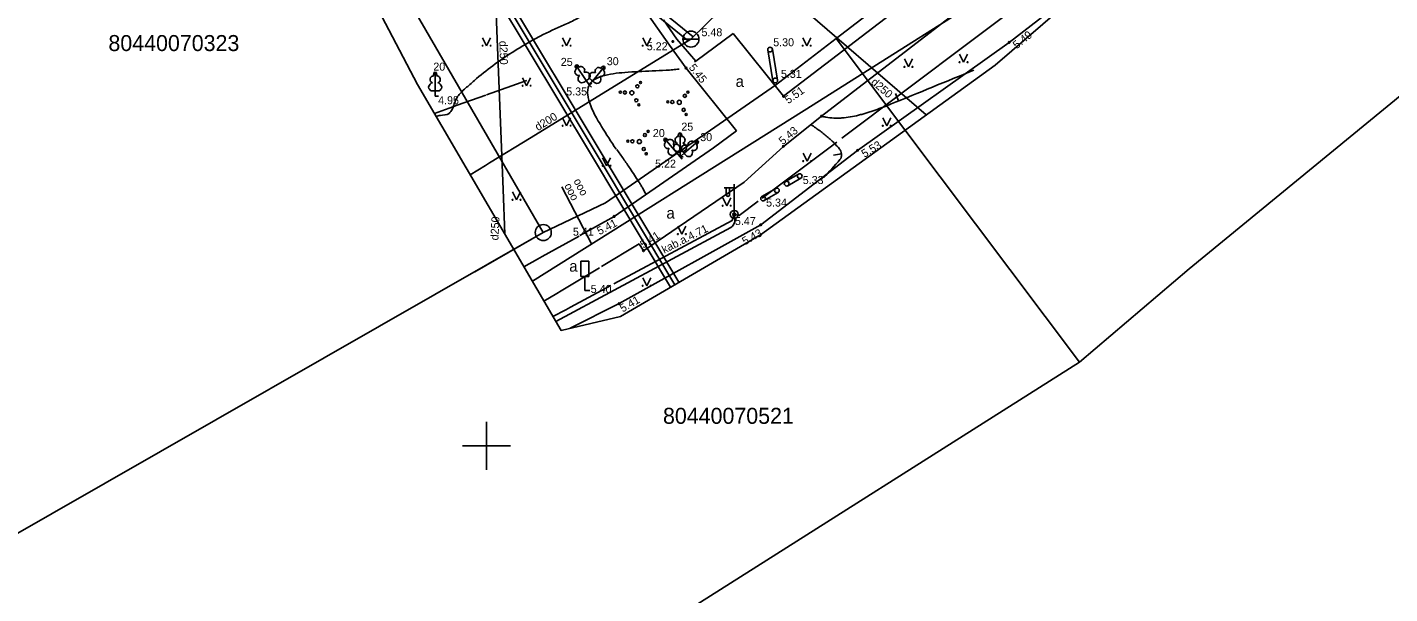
# Model space of a CAD drawing. Extents: x 519536 to 519949, y 326041 to 326519.
# Drawn here: x 519771.3 to 519856.4, y 326090.7 to 326126.2 of the extents above; entities that cross this region are included whole.
import ezdxf

# ---------------------------------------------------------------- set-up
doc = ezdxf.new("R2010")
doc.units = 0
for name, color, linetype in [('APGR_ELEM_####_####_#', 7, 'Continuous'), ('APGR_SARK_####_####_#', 7, 'Continuous'), ('APGS_ELEM_####_####_#', 7, 'Continuous'), ('APGS_VADP_ZSPR_####_#', 7, 'Continuous'), ('APGS_VADP_ZSPR_####_I', 7, 'Continuous'), ('APGS_VADP_ZSPR_TKST_I', 7, 'Continuous'), ('BUVE_ELEM_####_####_#', 7, 'Continuous'), ('CELI_CMAL_####_####_#', 7, 'Continuous'), ('CELI_CSEG_####_TKST_#', 7, 'Continuous'), ('CELI_ELEM_####_####_#', 7, 'Continuous'), ('CELI_SEGL_####_####_#', 7, 'Continuous'), ('CELI_ZIME_####_####_#', 7, 'Continuous'), ('GEOD_ELEM_####_####_#', 7, 'Continuous'), ('RAMI_UZMR_####_####_#', 7, 'Continuous'), ('RELJ_AATZ_####_TKST_#', 7, 'Continuous'), ('RELJ_ELEM_####_####_#', 7, 'Continuous'), ('RELJ_HORZ_PAMT_####_#', 7, 'Continuous'), ('ROBZ_PROJ_####_####_#', 7, 'Continuous'), ('ROBZ_PROJ_####_TKST_#', 7, 'Continuous'), ('ROBZ_UZMR_####_####_#', 7, 'Continuous'), ('ROBZ_UZMR_####_TKST_#', 7, 'Continuous'), ('SAKK_IZVK_####_TKST_#', 7, 'Continuous'), ('SAKK_KKAN_####_####_#', 7, 'Continuous'), ('SAKT_VADP_NEDR_####_#', 7, 'Continuous'), ('SKAN_VADP_PAST_####_#', 7, 'Continuous'), ('SKAN_VADP_PAST_####_I', 7, 'Continuous'), ('SKAN_VADP_PAST_TKST_#', 7, 'Continuous'), ('SKAN_VADP_PAST_TKST_I', 7, 'Continuous'), ('TERT_DIAM_####_TKST_#', 7, 'Continuous'), ('TERT_ELEM_####_####_#', 7, 'Continuous'), ('TERT_KONT_####_####_#', 7, 'Continuous'), ('TERT_KRND_####_####_#', 7, 'Continuous'), ('UDTK_ELEM_####_####_#', 7, 'Continuous'), ('UDTK_ELEM_####_TKST_#', 7, 'Continuous'), ('UDTK_VADP_UDEN_####_#', 7, 'Continuous'), ('UDTK_VADP_UDEN_TKST_#', 7, 'Continuous')]:
    doc.layers.add(name, color=color, linetype=linetype)

msp = doc.modelspace()

# ---------------------------------------------------------------- linework, layer by layer
at = {"layer": 'APGR_ELEM_####_####_#'}
msp.add_circle((519803.54, 326113.32), 0.5, dxfattribs=at)
at = {"layer": 'APGR_SARK_####_####_#'}
for p, q in [((519803.539, 326113.32), (519783.534, 326147.79)), ((519799.257, 326110.872), (519803.539, 326113.32))]:
    msp.add_line(p, q, dxfattribs=at)
at = {"layer": 'APGS_ELEM_####_####_#'}
for p, q in [((519815.476, 326116.123), (519814.841, 326116.118)), ((519814.976, 326116.119), (519814.976, 326115.727)), ((519815.186, 326116.121), (519815.186, 326115.727)), ((519815.476, 326114.456), (519815.476, 326116.339))]:
    msp.add_line(p, q, dxfattribs=at)
for radius in [0.25, 0.09]:
    msp.add_circle((519815.476, 326114.456), radius, dxfattribs=at)
msp.add_ellipse((519815.081, 326115.727), major_axis=(0, 0.151), ratio=0.695971, start_param=1.570796, end_param=4.712389, dxfattribs=at)
at = {"layer": 'APGS_VADP_ZSPR_####_#'}
for p, q in [((519817.215, 326115.469), (519821.877, 326118.979)), ((519815.786, 326114.393), (519816.972, 326115.286)), ((519807.949, 326110.114), (519815.34, 326114.084)), ((519815.34, 326114.084), (519815.476, 326114.456)), ((519815.476, 326114.456), (519815.786, 326114.393)), ((519805.237, 326108.657), (519807.759, 326110.012)), ((519804.144, 326108.071), (519804.943, 326108.5)), ((519804.943, 326108.499), (519805.237, 326108.657))]:
    msp.add_line(p, q, dxfattribs=at)
msp.add_lwpolyline([(519822.193, 326119.217), (519834.343, 326128.364), (519835.607, 326129.316)], dxfattribs=at)
at = {"layer": 'APGS_VADP_ZSPR_####_I'}
for points in [[(519815.511, 326114.135), (519815.506, 326113.991), (519815.457, 326113.848), (519815.367, 326113.726), (519815.251, 326113.64)], [(519815.511, 326114.135), (519815.476, 326114.456)], [(519804.322, 326107.766), (519815.251, 326113.64)]]:
    msp.add_lwpolyline(points, dxfattribs=at)
at = {"layer": 'BUVE_ELEM_####_####_#'}
for centre in [(519817.71, 326124.758), (519818.036, 326122.824), (519819.569, 326116.852), (519818.141, 326115.954), (519818.751, 326116.378), (519817.278, 326115.446)]:
    msp.add_circle(centre, 0.148, dxfattribs=at)
at = {"layer": 'CELI_CMAL_####_####_#'}
for p, q in [((519815.478, 326125.668), (519815.4, 326125.765)), ((519818.554, 326121.841), (519815.4, 326125.765)), ((519815.612, 326119.681), (519812.465, 326123.597)), ((519808.282, 326108.879), (519817.13, 326113.802)), ((519809.798, 326112.186), (519809.533, 326112.624)), ((519803.58, 326109.036), (519804.379, 326109.511)), ((519805.225, 326107.34), (519808.282, 326108.879))]:
    msp.add_line(p, q, dxfattribs=at)
for points in [[(519803.048, 326140.696), (519806.405, 326132.206), (519810.67, 326126.102)], [(519818.554, 326121.841), (519828.619, 326129.557), (519832.661, 326132.764)], [(519834.281, 326130.959), (519829.979, 326127.581), (519820.927, 326120.594)], [(519823.18, 326118.459), (519832.654, 326125.205), (519836.503, 326128.205)], [(519810.67, 326126.102), (519811.417, 326125.034), (519812.465, 326123.597)], [(519811.049, 326126.606), (519811.891, 326125.402), (519813.064, 326124.039)], [(519813.064, 326124.039), (519815.4, 326125.765)], [(519820.927, 326120.594), (519818.542, 326118.707), (519816.086, 326116.475)], [(519815.612, 326119.681), (519814.169, 326118.621)], [(519814.169, 326118.621), (519807.967, 326114.328)], [(519823.18, 326118.459), (519817.13, 326113.802)], [(519816.086, 326116.475), (519809.798, 326112.186)], [(519805.824, 326113.134), (519807.967, 326114.328)], [(519803.464, 326111.818), (519805.773, 326113.105)], [(519807.182, 326111.204), (519809.533, 326112.624)], [(519802.327, 326111.184), (519803.181, 326111.66)], [(519803.181, 326111.66), (519803.464, 326111.818)], [(519804.662, 326109.682), (519807.046, 326111.122)], [(519804.379, 326109.511), (519804.662, 326109.682)]]:
    msp.add_lwpolyline(points, dxfattribs=at)
at = {"layer": 'CELI_ELEM_####_####_#'}
for p, q in [((519806.381, 326111.537), (519805.881, 326111.537)), ((519805.881, 326110.568), (519805.881, 326111.537)), ((519806.381, 326110.568), (519806.381, 326111.537)), ((519806.381, 326110.568), (519805.881, 326110.568)), ((519806.135, 326110.568), (519806.135, 326109.69)), ((519806.135, 326109.69), (519806.45, 326109.69))]:
    msp.add_line(p, q, dxfattribs=at)
at = {"layer": 'CELI_SEGL_####_####_#'}
msp.add_line((519812.999, 326123.991), (519813.064, 326124.039), dxfattribs=at)
at = {"layer": 'CELI_ZIME_####_####_#'}
for p, q in [((519817.564, 326124.733), (519817.89, 326122.799)), ((519817.856, 326124.782), (519818.182, 326122.848)), ((519818.677, 326116.506), (519819.495, 326116.98)), ((519818.826, 326116.25), (519819.643, 326116.724)), ((519818.066, 326116.082), (519817.203, 326115.574)), ((519818.217, 326115.827), (519817.353, 326115.318))]:
    msp.add_line(p, q, dxfattribs=at)
at = {"layer": 'GEOD_ELEM_####_####_#'}
for p, q in [((519800, 326101.5), (519800, 326100)), ((519798.5, 326100), (519800, 326100)), ((519800, 326100), (519800, 326098.5)), ((519800, 326100), (519801.5, 326100))]:
    msp.add_line(p, q, dxfattribs=at)
at = {"layer": 'RAMI_UZMR_####_####_#'}
msp.add_lwpolyline([(519873.021, 326209.453), (519881.37, 326184.273), (519884.229, 326177.508), (519883.353, 326172.044), (519868.284, 326155.201), (519831.787, 326123.789), (519817.117, 326113.183), (519808.359, 326108.08), (519804.649, 326107.204), (519795.685, 326122.565), (519782.956, 326146.875), (519761.4, 326134.85), (519741.243, 326123.664), (519728.435, 326146.148), (519720.513, 326144.604), (519669.064, 326119.018)], dxfattribs=at)
at = {"layer": 'RELJ_ELEM_####_####_#'}
for centre in [(519811.636, 326125.262), (519832.654, 326125.205), (519812.465, 326123.597), (519818.554, 326121.841), (519820.927, 326120.594), (519818.542, 326118.707), (519823.18, 326118.459), (519807.967, 326114.328), (519817.13, 326113.802), (519809.798, 326112.186), (519808.282, 326108.879)]:
    msp.add_circle(centre, 0.05, dxfattribs=at)
at = {"layer": 'RELJ_HORZ_PAMT_####_#'}
for p, q in [((519825.541, 326122.006), (519825.73, 326121.543)), ((519821.673, 326118.167), (519822.168, 326118.238))]:
    msp.add_line(p, q, dxfattribs=at)
for points in [[(519796.84, 326120.586), (519797.106, 326120.637), (519797.649, 326120.767), (519797.761, 326120.883), (519797.899, 326121.146), (519798, 326121.429), (519798.111, 326121.704), (519798.278, 326121.943), (519798.817, 326122.459), (519799.373, 326122.95), (519800.535, 326123.859), (519801.756, 326124.681), (519803.031, 326125.424), (519803.766, 326125.808), (519804.518, 326126.15), (519805.271, 326126.495), (519806.008, 326126.888), (519806.456, 326127.174), (519806.885, 326127.487), (519807.66, 326128.203)], [(519820.932, 326120.598), (519820.943, 326120.595), (519821.07, 326120.56), (519821.198, 326120.532), (519821.7, 326120.476), (519821.952, 326120.472), (519822.203, 326120.483), (519822.725, 326120.543), (519823.241, 326120.655), (519823.504, 326120.727), (519823.764, 326120.803), (519824.021, 326120.884), (519824.276, 326120.972), (519824.781, 326121.16), (519825.271, 326121.356), (519830.45, 326123.47)], [(519821.06, 326116.75), (519822.082, 326117.887), (519822.108, 326117.92), (519822.129, 326117.958), (519822.145, 326117.998), (519822.159, 326118.039), (519822.169, 326118.085), (519822.174, 326118.132), (519822.17, 326118.224), (519822.125, 326118.409), (519822.085, 326118.493), (519822.035, 326118.566), (519821.928, 326118.69), (519821.818, 326118.811), (519821.704, 326118.928), (519821.586, 326119.041), (519821.344, 326119.26), (519821.092, 326119.468), (519820.963, 326119.568), (519820.833, 326119.668), (519820.568, 326119.861), (519820.267, 326120.072)]]:
    msp.add_spline(points, degree=3, dxfattribs=at)
at = {"layer": 'ROBZ_PROJ_####_####_#'}
for p, q in [((519821.833, 326125.441), (519831.642, 326133.008)), ((519818.058, 326122.529), (519821.833, 326125.441)), ((519821.833, 326125.441), (519837.056, 326105.226)), ((519860.226, 326124.449), (519843.903, 326111.053)), ((519807.437, 326115.177), (519818.058, 326122.529)), ((519803.539, 326113.32), (519807.437, 326115.177)), ((519764.294, 326090.885), (519803.539, 326113.32)), ((519843.903, 326111.053), (519837.056, 326105.226)), ((519837.056, 326105.226), (519812.114, 326089.425))]:
    msp.add_line(p, q, dxfattribs=at)
at = {"layer": 'ROBZ_UZMR_####_####_#'}
for p, q in [((519803.539, 326113.32), (519783.534, 326147.79)), ((519831.642, 326133.008), (519821.833, 326125.441)), ((519821.833, 326125.441), (519818.058, 326122.529)), ((519818.058, 326122.529), (519807.437, 326115.177)), ((519807.437, 326115.177), (519803.539, 326113.32)), ((519803.539, 326113.32), (519764.294, 326090.885))]:
    msp.add_line(p, q, dxfattribs=at)
at = {"layer": 'SAKK_IZVK_####_TKST_#'}
msp.add_line((519804.705, 326116.186), (519806.567, 326112.566), dxfattribs=at)
at = {"layer": 'SAKK_KKAN_####_####_#'}
msp.add_lwpolyline([(519802.857, 326110.275), (519819.847, 326120.948), (519840.354, 326133.938)], dxfattribs=at)
at = {"layer": 'SAKT_VADP_NEDR_####_#'}
for p, q in [((519797.926, 326133.126), (519806.771, 326118.375)), ((519798.112, 326133.4), (519807.038, 326118.511)), ((519798.299, 326131.921), (519806.549, 326118.161))]:
    msp.add_line(p, q, dxfattribs=at)
for points in [[(519806.771, 326118.375), (519811.756, 326110.06)], [(519807.038, 326118.511), (519812.015, 326110.211)], [(519806.549, 326118.161), (519811.497, 326109.909)]]:
    msp.add_lwpolyline(points, dxfattribs=at)
at = {"layer": 'SKAN_VADP_PAST_####_#'}
for p, q in [((519801.028, 326116.009), (519800.501, 326129.281)), ((519801.139, 326113.219), (519801.028, 326116.009))]:
    msp.add_line(p, q, dxfattribs=at)
at = {"layer": 'SKAN_VADP_PAST_####_I'}
msp.add_lwpolyline([(519827.476, 326120.673), (519818.86, 326128.106), (519818.447, 326128.393)], dxfattribs=at)
at = {"layer": 'TERT_ELEM_####_####_#'}
for p, q in [((519799.75, 326125.5), (519800, 326125)), ((519800, 326125), (519800.25, 326125.5)), ((519804.75, 326125.5), (519805, 326125)), ((519805, 326125), (519805.25, 326125.5)), ((519809.75, 326125.5), (519810, 326125)), ((519810, 326125), (519810.25, 326125.5)), ((519819.75, 326125.5), (519820, 326125)), ((519820, 326125), (519820.25, 326125.5)), ((519829.555, 326124.463), (519829.805, 326123.963)), ((519829.805, 326123.963), (519830.055, 326124.463)), ((519826.107, 326124.173), (519826.357, 326123.673)), ((519826.357, 326123.673), (519826.607, 326124.173)), ((519802.25, 326123), (519802.5, 326122.5)), ((519802.5, 326122.5), (519802.75, 326123)), ((519806.213, 326122.832), (519806.406, 326122.544)), ((519806.626, 326122.812), (519806.406, 326122.544)), ((519806.406, 326122.544), (519806.572, 326122.655)), ((519806.406, 326122.544), (519806.561, 326122.417)), ((519796.782, 326122.188), (519796.782, 326121.841)), ((519796.782, 326121.841), (519796.982, 326121.841)), ((519804.75, 326120.5), (519805, 326120)), ((519805, 326120), (519805.25, 326120.5)), ((519824.75, 326120.5), (519825, 326120)), ((519825, 326120), (519825.25, 326120.5)), ((519811.858, 326118.323), (519812.084, 326118.06)), ((519812.084, 326118.407), (519812.084, 326118.06)), ((519812.347, 326118.286), (519812.084, 326118.06)), ((519819.787, 326118.29), (519820.037, 326117.79)), ((519820.037, 326117.79), (519820.287, 326118.29)), ((519807.25, 326118), (519807.5, 326117.5)), ((519807.5, 326117.5), (519807.75, 326118)), ((519812.084, 326118.06), (519812.236, 326118.19)), ((519812.084, 326118.06), (519812.284, 326118.06)), ((519812.084, 326118.06), (519812.214, 326117.908)), ((519801.623, 326115.873), (519801.873, 326115.373)), ((519801.873, 326115.373), (519802.123, 326115.873)), ((519814.75, 326115.5), (519815, 326115)), ((519815, 326115), (519815.25, 326115.5)), ((519811.954, 326113.725), (519812.204, 326113.225)), ((519812.204, 326113.225), (519812.454, 326113.725)), ((519809.75, 326110.5), (519810, 326110)), ((519810, 326110), (519810.25, 326110.5))]:
    msp.add_line(p, q, dxfattribs=at)
for points in [[(519805.57, 326123.789), (519806.213, 326122.832)], [(519805.774, 326123.646), (519805.772, 326123.647)], [(519807.357, 326123.704), (519806.626, 326122.812)], [(519807.279, 326123.468), (519807.279, 326123.469)], [(519796.782, 326123.341), (519796.782, 326122.188)], [(519796.872, 326123.109), (519796.871, 326123.11)], [(519811.105, 326119.197), (519811.858, 326118.323)], [(519812.084, 326119.56), (519812.084, 326118.407)], [(519812.174, 326119.328), (519812.173, 326119.329)], [(519811.325, 326119.079), (519811.323, 326119.079)], [(519813.221, 326119.039), (519812.347, 326118.286)], [(519813.103, 326118.819), (519813.103, 326118.821)]]:
    msp.add_lwpolyline(points, dxfattribs=at)
for centre, radius in [((519799.75, 326125), 0.028), ((519800.25, 326125), 0.0263), ((519804.75, 326125), 0.028), ((519805.25, 326125), 0.0263), ((519809.75, 326125), 0.028), ((519810.25, 326125), 0.0263), ((519819.75, 326125), 0.028), ((519820.25, 326125), 0.0263), ((519826.107, 326123.673), 0.028), ((519826.607, 326123.673), 0.0263), ((519829.555, 326123.963), 0.028), ((519830.055, 326123.963), 0.0263), ((519809.421, 326122.463), 0.096), ((519809.618, 326122.695), 0.064), ((519802.25, 326122.5), 0.028), ((519802.75, 326122.5), 0.0263), ((519808.355, 326122.09), 0.064), ((519808.64, 326122.076), 0.096), ((519809.074, 326122.056), 0.128), ((519809.35, 326121.589), 0.096), ((519812.384, 326121.866), 0.096), ((519812.581, 326122.098), 0.064), ((519809.508, 326121.299), 0.064), ((519811.318, 326121.493), 0.064), ((519811.603, 326121.479), 0.096), ((519812.037, 326121.458), 0.128), ((519812.313, 326120.991), 0.096), ((519804.75, 326120), 0.028), ((519805.25, 326120), 0.0263), ((519812.471, 326120.702), 0.064), ((519824.75, 326120), 0.028), ((519825.25, 326120), 0.0263), ((519809.543, 326119.005), 0.128), ((519809.89, 326119.413), 0.096), ((519810.087, 326119.644), 0.064), ((519808.824, 326119.039), 0.064), ((519809.109, 326119.026), 0.096), ((519809.819, 326118.538), 0.096), ((519809.977, 326118.249), 0.064), ((519807.25, 326117.5), 0.028), ((519807.75, 326117.5), 0.0263), ((519819.786, 326117.789), 0.028), ((519820.286, 326117.789), 0.0263), ((519801.623, 326115.373), 0.028), ((519802.123, 326115.373), 0.0263), ((519814.75, 326115), 0.028), ((519815.25, 326115), 0.0263), ((519811.953, 326113.225), 0.028), ((519812.453, 326113.225), 0.0263), ((519809.75, 326110), 0.028), ((519810.25, 326110), 0.0263)]:
    msp.add_circle(centre, radius, dxfattribs=at)
for centre, major_axis, ratio, start_param, end_param in [((519805.711, 326123.349), (0.086, -0.198), 0.861323, 3.141593, 6.283185), ((519805.654, 326123.665), (0.084, -0.124), 0.707107, 3.14537, 5.287485), ((519805.653, 326123.665), (0.084, -0.124), 0.707107, 0.995701, 3.137816), ((519805.924, 326123.492), (0.151, -0.155), 0.861323, 0, 3.141593), ((519806.976, 326123.441), (-0.165, -0.14), 0.861323, 3.141593, 6.283185), ((519807.174, 326123.279), (-0.105, -0.189), 0.861323, 0, 3.141593), ((519807.262, 326123.588), (-0.095, -0.116), 0.707107, 3.14537, 5.287485), ((519807.262, 326123.588), (-0.095, -0.116), 0.707107, 0.995701, 3.137816), ((519796.692, 326122.434), (0.307, 0.095), 0.814445, 1.570796, 4.752015), ((519796.654, 326122.896), (-0.039, -0.212), 0.861323, 3.141593, 6.283185), ((519796.782, 326123.191), (0, -0.15), 0.707107, 3.14537, 5.287485), ((519796.782, 326123.191), (0, -0.15), 0.707107, 0.995701, 3.137816), ((519796.872, 326122.434), (-0.307, 0.095), 0.814445, 1.531171, 4.712389), ((519796.91, 326122.896), (0.039, -0.212), 0.861323, 0, 3.141593), ((519806.001, 326122.986), (0.202, 0.25), 0.814445, 1.570796, 4.752015), ((519806.15, 326123.086), (-0.308, -0.092), 0.814445, 1.531171, 4.712389), ((519806.713, 326123.059), (0.298, -0.121), 0.814445, 1.570796, 4.752015), ((519806.851, 326122.946), (-0.177, 0.268), 0.814445, 1.531171, 4.712389), ((519811.203, 326119.083), (0.098, -0.114), 0.707107, 3.14537, 5.287485), ((519811.203, 326119.083), (0.098, -0.114), 0.707107, 0.995701, 3.137816), ((519811.493, 326118.943), (0.168, -0.136), 0.861323, 0, 3.141593), ((519811.956, 326119.115), (-0.039, -0.212), 0.861323, 3.141593, 6.283185), ((519812.084, 326119.41), (0, -0.15), 0.707107, 3.14537, 5.287485), ((519812.084, 326119.41), (0, -0.15), 0.707107, 0.995701, 3.137816), ((519812.212, 326119.115), (0.039, -0.212), 0.861323, 0, 3.141593), ((519811.298, 326118.776), (0.109, -0.186), 0.861323, 3.141593, 6.283185), ((519811.629, 326118.451), (0.17, 0.272), 0.814445, 1.570796, 4.752015), ((519811.994, 326118.653), (0.307, 0.095), 0.814445, 1.570796, 4.752015), ((519811.765, 326118.568), (-0.295, -0.128), 0.814445, 1.531171, 4.712389), ((519812.174, 326118.653), (-0.307, 0.095), 0.814445, 1.531171, 4.712389), ((519812.475, 326118.515), (0.272, -0.17), 0.814445, 1.570796, 4.752015), ((519812.592, 326118.379), (-0.128, 0.295), 0.814445, 1.531171, 4.712389), ((519812.8, 326118.846), (-0.186, -0.109), 0.861323, 3.141593, 6.283185), ((519812.967, 326118.651), (-0.136, -0.168), 0.861323, 0, 3.141593), ((519813.107, 326118.941), (-0.114, -0.098), 0.707107, 3.14537, 5.287485), ((519813.107, 326118.941), (-0.114, -0.098), 0.707107, 0.995701, 3.137816)]:
    msp.add_ellipse(centre, major_axis=major_axis, ratio=ratio, start_param=start_param, end_param=end_param, dxfattribs=at)
at = {"layer": 'TERT_KONT_####_####_#'}
for points in [[(519812.023, 326123.534), (519811.628, 326123.494), (519811.214, 326123.463), (519810.351, 326123.419), (519808.633, 326123.327), (519807.206, 326123.09), (519806.707, 326122.866), (519806.529, 326122.719), (519806.46, 326122.635), (519806.431, 326122.59), (519806.418, 326122.567), (519806.406, 326122.544), (519806.354, 326122.412), (519806.322, 326122.27), (519806.317, 326121.957), (519806.508, 326121.232), (519806.914, 326120.4), (519807.179, 326119.954), (519808.085, 326118.53)], [(519808.134, 326118.522), (519808.549, 326117.927), (519808.96, 326117.329), (519809.507, 326116.496), (519809.626, 326116.303), (519809.742, 326116.107), (519809.962, 326115.709)]]:
    msp.add_spline(points, degree=3, dxfattribs=at)
at = {"layer": 'TERT_KRND_####_####_#'}
for points in [[(519799.984, 326121.925), (519802.513, 326122.827)], [(519798.159, 326121.275), (519799.949, 326121.913)], [(519796.735, 326120.766), (519797.878, 326121.174)], [(519797.878, 326121.175), (519798.159, 326121.275)]]:
    msp.add_lwpolyline(points, dxfattribs=at)
at = {"layer": 'UDTK_ELEM_####_####_#'}
msp.add_line((519812.27, 326125.41), (519813.27, 326125.41), dxfattribs=at)
msp.add_circle((519812.77, 326125.41), 0.5, dxfattribs=at)
at = {"layer": 'UDTK_VADP_UDEN_####_#'}
for p, q in [((519812.769, 326125.41), (519827.278, 326139.636)), ((519812.769, 326125.41), (519802.78, 326119.272)), ((519802.78, 326119.272), (519800.179, 326117.674)), ((519799.919, 326117.513), (519798.973, 326116.931)), ((519800.179, 326117.674), (519799.918, 326117.513))]:
    msp.add_line(p, q, dxfattribs=at)
for points in [[(519767.203, 326162.23), (519778.16, 326153.314), (519799.72, 326135.77), (519812.588, 326125.299)], [(519767.47, 326162.528), (519778.412, 326153.624), (519799.945, 326136.103), (519812.913, 326125.551)]]:
    msp.add_lwpolyline(points, dxfattribs=at)

# ---------------------------------------------------------------- texts
at = {"layer": 'APGS_VADP_ZSPR_TKST_I'}
msp.add_text('kab.a.4.71', height=0.5, rotation=26.79331, dxfattribs=at).set_placement((519811.098, 326111.996))
at = {"layer": 'CELI_CSEG_####_TKST_#'}
for p in [(519815.559, 326122.426), (519811.234, 326114.195), (519805.161, 326110.875)]:
    msp.add_text('a', height=0.7, dxfattribs=at).set_placement(p)
at = {"layer": 'RELJ_AATZ_####_TKST_#'}
for s, p in [(' 5.22', (519809.821, 326124.713)), (' 5.30', (519817.722, 326124.964)), (' 5.31', (519818.202, 326122.989)), (' 4.95', (519796.782, 326121.341)), (' 5.35', (519804.787, 326121.89)), (' 5.22', (519810.342, 326117.379)), (' 5.33', (519819.569, 326116.352)), (' 5.34', (519817.278, 326114.946)), (' 5.47', (519815.329, 326113.791)), (' 5.41', (519805.204, 326113.125)), (' 5.40', (519806.316, 326109.547))]:
    msp.add_text(s, height=0.5, dxfattribs=at).set_placement(p)
for s, rotation, p in [('5.49', 38.67242, (519833.127, 326124.77)), (' 5.45', 308.78332, (519812.487, 326123.767)), ('5.51', 35.2815, (519818.849, 326121.339)), (' 5.43', 40.25748, (519818.367, 326118.655)), ('5.53', 31.01616, (519823.606, 326117.986)), (' 5.41', 27.6996, (519806.889, 326113.067)), (' 5.41', 32.62504, (519809.633, 326112.206)), (' 5.43', 29.04698, (519815.971, 326112.425)), (' 5.41', 29.84277, (519808.338, 326108.229))]:
    msp.add_text(s, height=0.5, rotation=rotation, dxfattribs=at).set_placement(p)
at = {"layer": 'ROBZ_PROJ_####_TKST_#'}
msp.add_text('80440070521', height=1, dxfattribs=at).set_placement((519811.019, 326101.367))
at = {"layer": 'ROBZ_UZMR_####_TKST_#'}
msp.add_text('80440070323', height=1, dxfattribs=at).set_placement((519776.363, 326124.664))
at = {"layer": 'SAKK_IZVK_####_TKST_#'}
for p in [(519805.416, 326116.552), (519804.838, 326116.255)]:
    msp.add_text('ooo', height=0.5, rotation=297.22204, dxfattribs=at).set_placement(p)
at = {"layer": 'SKAN_VADP_PAST_TKST_#'}
for rotation, p in [(271.63037, (519800.792, 326125.294)), (87.08178, (519800.73, 326112.824))]:
    msp.add_text('d250', height=0.5, rotation=rotation, dxfattribs=at).set_placement(p)
at = {"layer": 'SKAN_VADP_PAST_TKST_I'}
msp.add_text('d250', height=0.5, rotation=319.21675, dxfattribs=at).set_placement((519823.978, 326122.654))
at = {"layer": 'TERT_DIAM_####_TKST_#'}
for s, p in [('25', (519804.633, 326123.737)), ('30', (519807.507, 326123.78)), (' 20', (519796.482, 326123.441)), ('25', (519812.167, 326119.688)), ('20', (519810.387, 326119.29)), ('30', (519813.348, 326119.036))]:
    msp.add_text(s, height=0.5, dxfattribs=at).set_placement(p)
at = {"layer": 'UDTK_ELEM_####_TKST_#'}
msp.add_text(' 5.48', height=0.5, dxfattribs=at).set_placement((519813.239, 326125.59))
at = {"layer": 'UDTK_VADP_UDEN_TKST_#'}
msp.add_text('d200', height=0.5, rotation=31.57047, dxfattribs=at).set_placement((519803.203, 326119.657))

doc.saveas('drawing.dxf')
